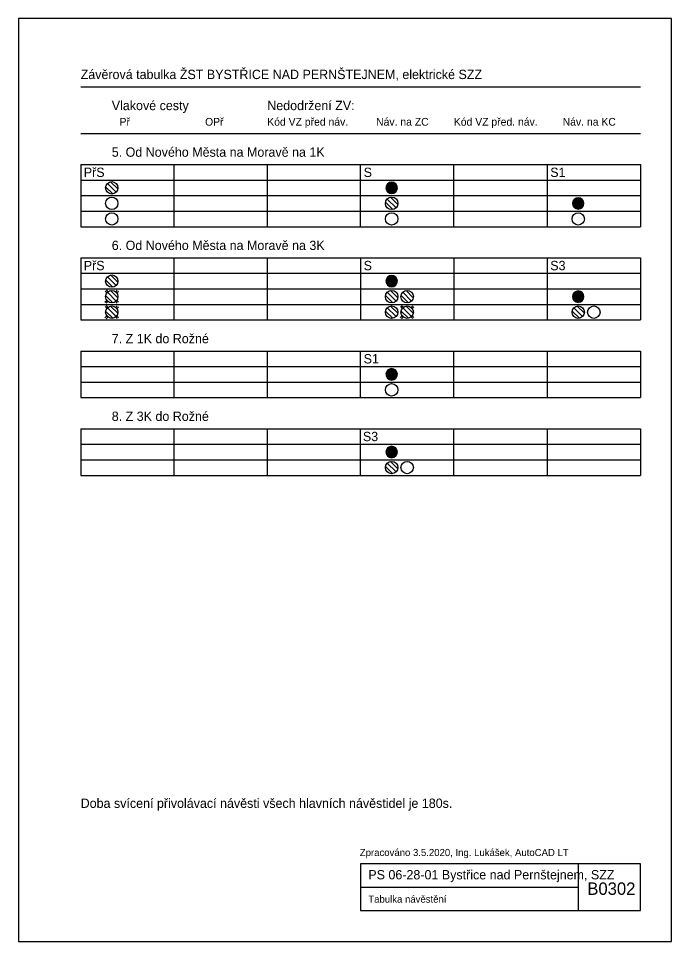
# Model space of a CAD drawing. Extents: x -591 to 5777, y 380 to 2087.
# Drawn here: x 630 to 840, y 380 to 677 of the extents above; entities that cross this region are included whole.
import ezdxf

# ---------------------------------------------------------------- set-up
doc = ezdxf.new("R2010")
doc.units = 0
for name, color, linetype in [('0B', 7, 'Continuous'), ('Implicitní', 7, 'Continuous'), ('Vrstva 63', 7, 'Continuous')]:
    doc.layers.add(name, color=color, linetype=linetype)

# ---------------------------------------------------------------- blocks, each defined once
blk = doc.blocks.new('ZT75')
at = {"layer": 'Implicitní'}
for points in [[(-18.1, 3.2), (18.1, 3.2)], [(-17.6, 0.7), (17.6, 0.7)], [(-17.3, 6.4), (17.3, 6.4)], [(-15.7, 9.6), (15.7, 9.6)], [(-14, 12), (14, 12)], [(-12.4, 13.6), (12.4, 13.6)], [(-10.4, 15.2), (10.4, 15.2)], [(-7.6, 16.8), (7.6, 16.8)], [(-18.1, -3.2), (18.1, -3.2)], [(-17.6, -0.7), (17.6, -0.7)], [(-17.3, -6.4), (17.3, -6.4)], [(-15.7, -9.6), (15.7, -9.6)], [(-14, -12), (14, -12)], [(-12.4, -13.6), (12.4, -13.6)], [(-10.4, -15.2), (10.4, -15.2)], [(-7.6, -16.8), (7.6, -16.8)]]:
    blk.add_lwpolyline(points, dxfattribs=at)
for start, end in [(0, 180), (180, 0)]:
    blk.add_arc((0, 0), 18.4, start, end, dxfattribs=at)
blk = doc.blocks.new('ZT76')
at = {"layer": 'Implicitní'}
for p, q in [((3.7, 19.7), (-19.7, -3.7)), ((14.1, 14.1), (-14.1, -14.1)), ((19.7, 3.7), (-3.7, -19.7))]:
    blk.add_line(p, q, dxfattribs=at)
blk.add_circle((0, 0), 20, dxfattribs=at)
blk = doc.blocks.new('ZT74')
at = {"layer": 'Implicitní'}
blk.add_circle((0, 0), 20, dxfattribs=at)
blk = doc.blocks.new('ZT78')
at = {"layer": 'Implicitní'}
for p, q in [((-30.7, 25.7), (-22.7, 17.7)), ((-25.7, 30.7), (-17.7, 22.7)), ((17.5, 21.7), (25.5, 29.7)), ((22.5, 16.7), (30.5, 24.7)), ((-31.3, -25.5), (-23.3, -17.5)), ((-26.3, -30.5), (-18.3, -22.5)), ((17.5, -21.7), (25.5, -29.7)), ((22.5, -16.7), (30.5, -24.7))]:
    blk.add_line(p, q, dxfattribs=at)

msp = doc.modelspace()

# ---------------------------------------------------------------- linework, layer by layer
at = {"layer": '0B'}
for p, q in [((650, 655), (830, 655)), ((650, 640), (830, 640)), ((650, 630), (830, 630)), ((650, 630), (650, 610)), ((680, 630), (680, 610)), ((710, 630), (710, 610)), ((740, 610), (740, 630)), ((770, 610), (770, 630)), ((800, 630), (800, 610)), ((830, 630), (830, 610)), ((650, 625), (830, 625)), ((650, 620), (830, 620)), ((650, 615), (830, 615)), ((650, 615), (830, 615)), ((650, 610), (830, 610)), ((650, 600), (830, 600)), ((650, 600), (650, 580)), ((680, 600), (680, 580)), ((710, 600), (710, 580)), ((740, 600), (740, 580)), ((770, 600), (770, 580)), ((800, 600), (800, 580)), ((830, 600), (830, 580)), ((650, 595), (830, 595)), ((650, 595), (830, 595)), ((650, 590), (830, 590)), ((650, 585), (830, 585)), ((650, 585), (830, 585)), ((650, 580), (830, 580)), ((650, 580), (830, 580)), ((650, 580), (830, 580)), ((650, 570), (830, 570)), ((650, 570), (650, 555)), ((680, 570), (680, 555)), ((710, 570), (710, 555)), ((740, 555), (740, 570)), ((770, 555), (770, 570)), ((800, 570), (800, 555)), ((830, 570), (830, 555)), ((650, 565), (830, 565)), ((650, 560), (830, 560)), ((650, 555), (830, 555)), ((650, 555), (830, 555)), ((650, 545), (830, 545)), ((650, 545), (650, 530)), ((680, 545), (680, 530)), ((710, 545), (710, 530)), ((740, 530), (740, 545)), ((770, 530), (770, 545)), ((800, 545), (800, 530)), ((830, 545), (830, 530)), ((650, 540), (830, 540)), ((650, 535), (830, 535)), ((650, 530), (830, 530)), ((650, 530), (830, 530)), ((830, 405), (740, 405)), ((740, 405), (740, 390)), ((810, 405), (810, 390)), ((830, 390), (830, 405)), ((740, 397.5), (810, 397.5)), ((740, 390), (830, 390))]:
    msp.add_line(p, q, dxfattribs=at)
at = {"layer": 'Vrstva 63'}
msp.add_lwpolyline([(630, 380), (840, 380), (840, 677), (630, 677)], close=True, dxfattribs=at)

# ---------------------------------------------------------------- block references
at = {"layer": '0B'}
for name, p, xscale, yscale, rotation in [('ZT76', (660, 622.5), 0.10000000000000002, 0.1, 89.99999999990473), ('ZT75', (750, 622.5), 0.1, 0.10000000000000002, -9.526953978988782e-11), ('ZT74', (660, 617.5), 0.1, 0.10000000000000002, -9.526953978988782e-11), ('ZT76', (750, 617.5), 0.10000000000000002, 0.1, 89.99999999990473), ('ZT75', (810, 617.5), 0.1, 0.10000000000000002, -9.526953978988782e-11), ('ZT74', (660, 612.5), 0.1, 0.10000000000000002, -9.526953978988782e-11), ('ZT74', (750, 612.5), 0.1, 0.10000000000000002, -9.526953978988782e-11), ('ZT74', (810, 612.5), 0.1, 0.10000000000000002, -9.526953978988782e-11), ('ZT76', (660, 592.5), 0.10000000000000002, 0.10000000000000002, 89.99999999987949), ('ZT75', (750, 592.5), 0.1, 0.10000000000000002, -1.2050326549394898e-10), ('ZT78', (660, 587.5), 0.06999999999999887, 0.06999999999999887, -1.2050326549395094e-10), ('ZT76', (660, 587.5), 0.10000000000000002, 0.10000000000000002, 89.99999999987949), ('ZT76', (750, 587.5), 0.10000000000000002, 0.10000000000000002, 89.99999999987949), ('ZT76', (755, 587.5), 0.10000000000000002, 0.10000000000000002, 89.99999999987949), ('ZT76', (755, 587.5), 0.10000000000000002, 0.10000000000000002, 89.99999999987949), ('ZT75', (810, 587.5), 0.1, 0.10000000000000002, -1.2050326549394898e-10), ('ZT78', (660, 582.5), 0.06999999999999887, 0.06999999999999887, -1.2050326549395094e-10), ('ZT76', (660, 582.5), 0.10000000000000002, 0.10000000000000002, 89.99999999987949), ('ZT76', (750, 582.5), 0.10000000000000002, 0.10000000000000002, 89.99999999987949), ('ZT78', (755, 582.5), 0.06999999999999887, 0.06999999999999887, -1.2050326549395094e-10), ('ZT76', (755, 582.5), 0.10000000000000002, 0.10000000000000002, 89.99999999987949), ('ZT76', (755, 582.5), 0.10000000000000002, 0.10000000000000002, 89.99999999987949), ('ZT76', (810, 582.5), 0.10000000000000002, 0.10000000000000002, 89.99999999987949), ('ZT74', (815, 582.5), 0.1, 0.10000000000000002, -1.2050326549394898e-10), ('ZT75', (750, 562.5), 0.1, 0.10000000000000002, -1.2050326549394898e-10), ('ZT74', (750, 557.5), 0.1, 0.10000000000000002, -1.2050326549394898e-10), ('ZT75', (750, 537.5), 0.1, 0.10000000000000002, -1.2050326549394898e-10), ('ZT76', (750, 532.5), 0.10000000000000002, 0.10000000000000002, 89.99999999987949), ('ZT74', (755, 532.5), 0.1, 0.10000000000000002, -1.2050326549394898e-10)]:
    msp.add_blockref(name, p, dxfattribs=dict(at, xscale=xscale, yscale=yscale, rotation=rotation))

# ---------------------------------------------------------------- texts
for s, height, p in [('Závěrová tabulka ŽST BYSTŘICE NAD PERNŠTEJNEM, elektrické SZZ', 3, (650, 657.5)), ('Vlakové cesty', 3, (660, 647.5)), ('Nedodržení ZV:', 3, (710, 647.5)), ('Př', 2.5, (662.5, 642.5)), ('OPř', 2.5, (690, 642.5)), ('Kód VZ před náv.', 2.5, (710, 642.5)), ('Náv. na ZC', 2.5, (745, 642.5)), ('Kód VZ před. náv.', 2.5, (770, 642.5)), ('Náv. na KC', 2.5, (805, 642.5)), ('5. Od Nového Města na Moravě na 1K', 3, (660, 632.5)), ('PřS', 3, (651, 626)), ('S', 3, (741, 626)), ('S1', 3, (801, 626)), ('6. Od Nového Města na Moravě na 3K', 3, (660, 602.5)), ('PřS', 3, (651, 596)), ('S', 3, (741, 596)), ('S3', 3, (801, 596)), ('7. Z 1K do Rožné', 3, (660, 572.5)), ('S1', 3, (741, 566)), ('8. Z 3K do Rožné', 3, (660, 547.5)), ('S3', 3, (740.75, 541)), ('Doba svícení přivolávací návěsti všech hlavních návěstidel je 180s.', 3, (650, 423)), ('Zpracováno 3.5.2020, Ing. Lukášek, AutoCAD LT', 2.2988, (739.77, 407.5)), ('PS 06-28-01 Bystřice nad Pernštejnem, SZZ', 3, (742.5, 400)), ('B0302', 4, (812.92, 395.02)), ('Tabulka návěstění', 2.3, (742.5, 392.5))]:
    msp.add_text(s, height=height, rotation=360, dxfattribs=at).set_placement(p)

doc.saveas('drawing.dxf')
